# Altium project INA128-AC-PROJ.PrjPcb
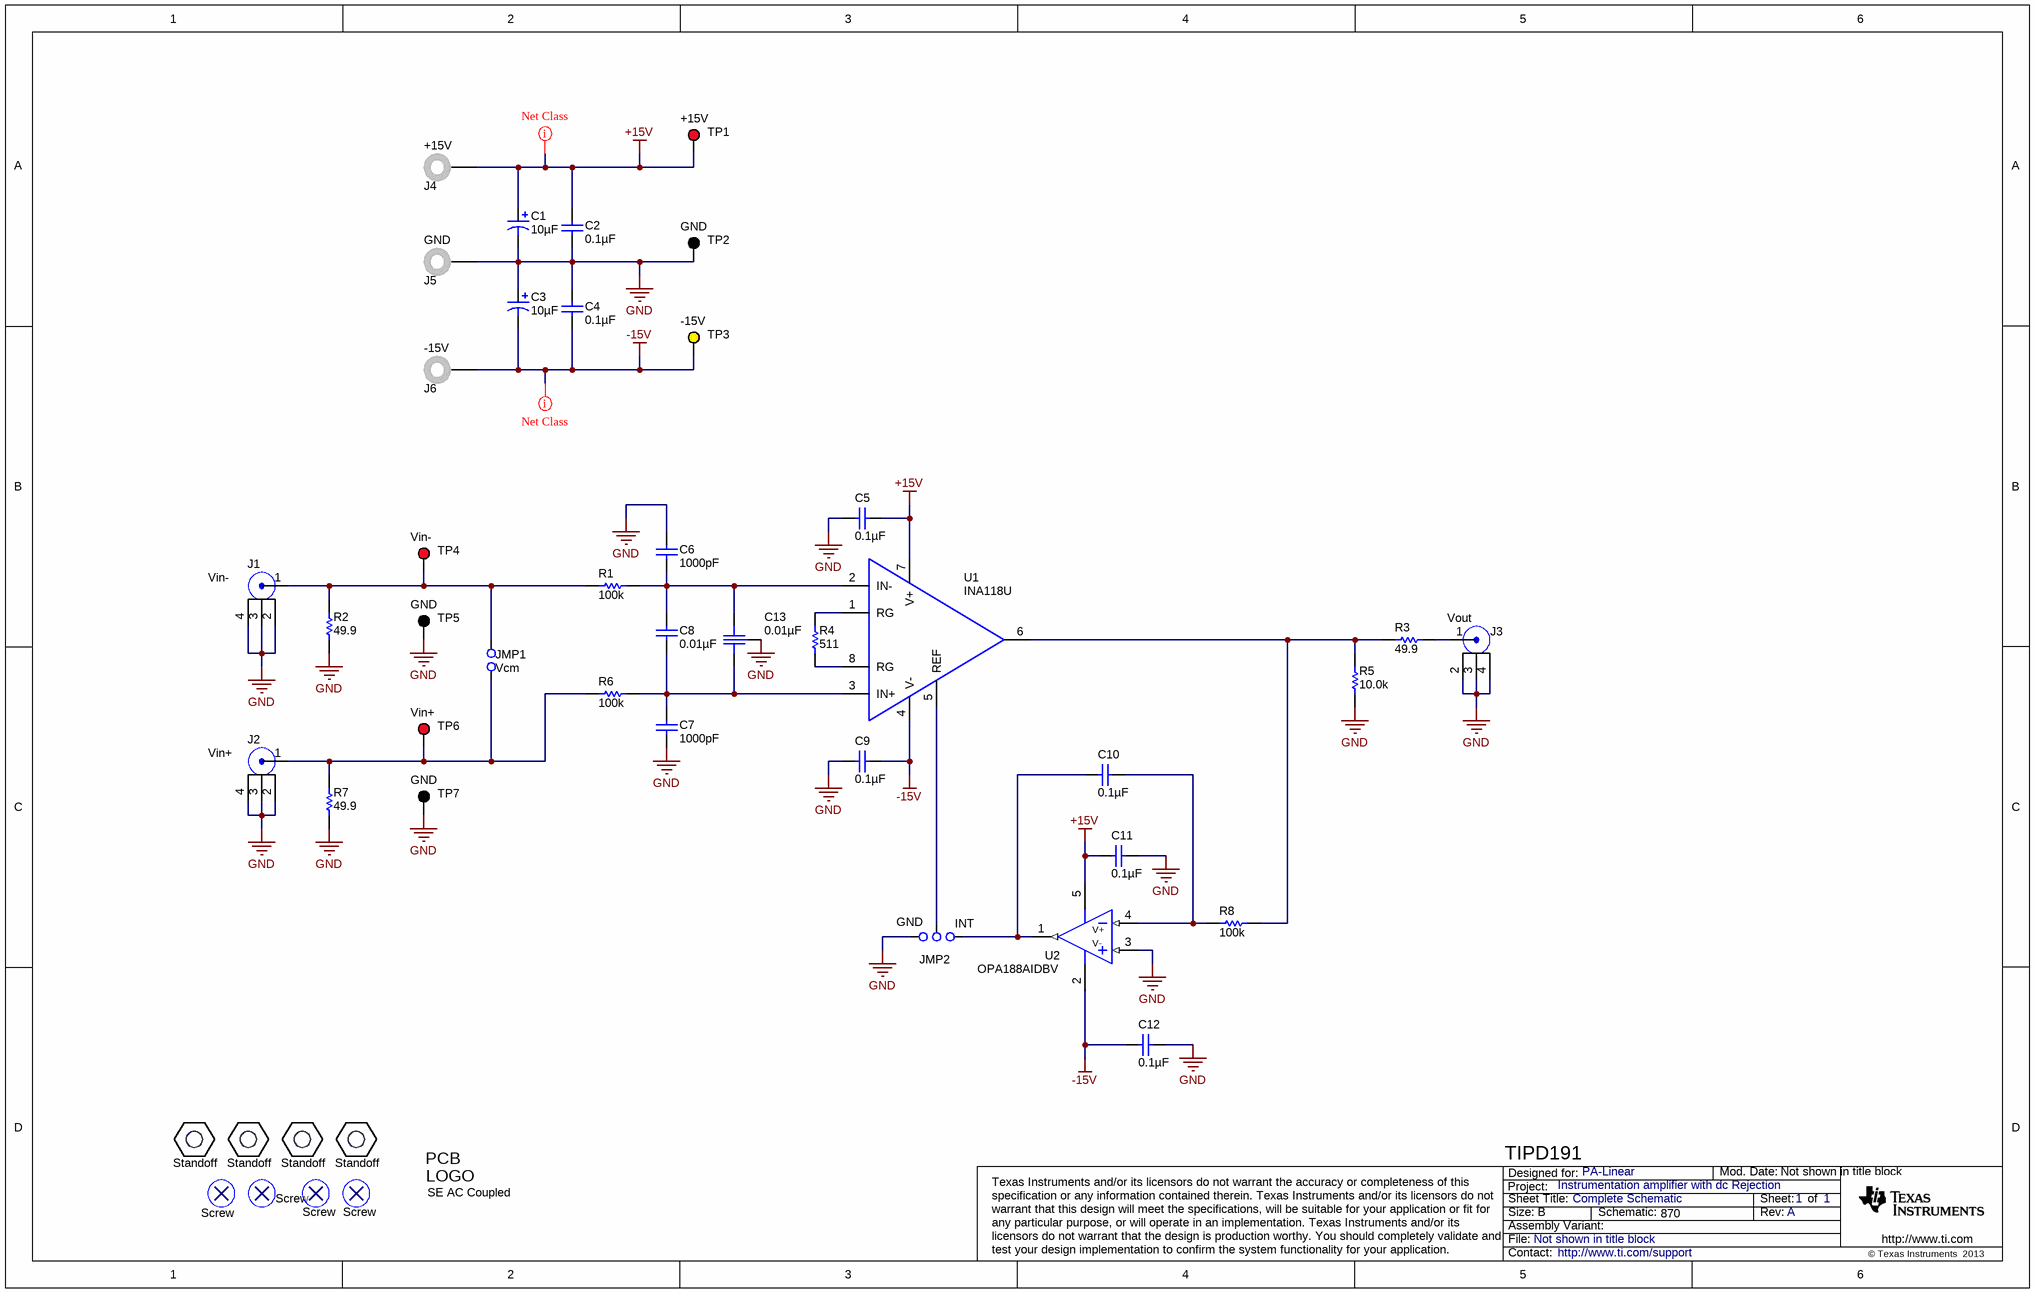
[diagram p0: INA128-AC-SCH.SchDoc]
TechSupport: http://www.ti.com/support; SCH_Rev: A; PRJ_Title: Instrumentation amplifier with dc Rejection; PRJ_Customer: PA-Linear; CopyrightYear: 2013
1 sheet, 47 parts. Net scope: global (net labels, ports and power ports of the same name join across sheets).
Board file: INA128-AC_PCB.PcbDoc

## Sheet INA128-AC-SCH.SchDoc: Complete Schematic
size B; Date: Not shown in title block; ApprovedBy: Not shown in title block; CheckedBy: Not shown in title block; Author: Not shown in title block; CompanyName: Not shown in title block; DrawnBy: Not shown in title block; Engineer: Not shown in title block; Organization: Not shown in title block; Address1: Not shown in title block; Address2: Not shown in title block; Address3: Not shown in title block; Address4: Not shown in title block; DocumentNumber: 1; Revision: Use project parameter SCH_Rev; SheetNumber: 1; SheetTotal: 1; PageSetup: Record=PageOptions|CenterHorizontal=True|CenterVertical=True|PrintScale=0.72|XCorrection=1.00|YCorrection=1.00|PrintKind=0|BorderSize=5000000|LeftOffset=0|BottomOffset=0|Orientation=2|PaperLength=1000|PaperWidth=1000|Scale=100|PaperSource=15|PrintQuality=600|MediaType=1|DitherType=10|PaperKind=Letter|PrintScaleMode=1

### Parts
C1  ValueDisplayed: 10µF  [7343-43]  (hidden comment: 293D106X9050E2TE3)
C2  ValueDisplayed: 0.1µF  [0603]  (hidden comment: 06033D104KAT2A)
C3  ValueDisplayed: 10µF  [7343-43]  (hidden comment: 293D106X9050E2TE3)
C4  ValueDisplayed: 0.1µF  [0603]  (hidden comment: 06033D104KAT2A)
C5  ValueDisplayed: 0.1µF  [0603]  (hidden comment: 06033D104KAT2A)
C6  ValueDisplayed: 1000pF  [0603]  (hidden comment: 06031C102JAT2A)
C7  ValueDisplayed: 1000pF  [0603]  (hidden comment: 06031C102JAT2A)
C8  ValueDisplayed: 0.01µF  [0603]  (hidden comment: 06031C103JAT2A)
C9  ValueDisplayed: 0.1µF  [0603]  (hidden comment: 06033D104KAT2A)
C10  ValueDisplayed: 0.1µF  [0603]  (hidden comment: 06033D104KAT2A)
C11  ValueDisplayed: 0.1µF  [0603]  (hidden comment: 06033D104KAT2A)
C12  ValueDisplayed: 0.1µF  [0603]  (hidden comment: 06033D104KAT2A)
C13  ValueDisplayed: 0.01µF  [X2Y_0603]  (hidden comment: 500X14W103MV4T)
J1  Vin-  [Right Angle BNC]
J2  Vin+  [Right Angle BNC]
J3  Vout  [Right Angle BNC]
J4  +15V  [JACK NON-INSULATED .218"]
J5  GND  [JACK NON-INSULATED .218"]
J6  -15V  [JACK NON-INSULATED .218"]
JMP1  Vcm  [Header 100mil, 1x2]
JMP2  GND  [JUMP3]
R1  ValueDisplayed: 100k  [0603]  (hidden comment: CPF0603B100KE)
R2  ValueDisplayed: 49.9  [0805]  (hidden comment: CRCW080549R9FKEA)
R3  ValueDisplayed: 49.9  [0805]  (hidden comment: CRCW080549R9FKEA)
R4  ValueDisplayed: 511  [0805]  (hidden comment: CRCW0805511RFKEA)
R5  ValueDisplayed: 10.0k  [0603]  (hidden comment: CRCW060310K0FKEA)
R6  ValueDisplayed: 100k  [0603]  (hidden comment: CPF0603B100KE)
R7  ValueDisplayed: 49.9  [0805]  (hidden comment: CRCW080549R9FKEA)
R8  ValueDisplayed: 100k  [0603]  (hidden comment: CRCW06031M00FKEA)
TIPD191  SE AC Coupled  [TI_Symbol_Overlay_Small]  (no BOM)
TP1  +15V  [Keystone5005]
TP2  GND  [Keystone5006]
TP3  -15V  [Keystone5009]
TP4  Vin-  [Keystone5005]
TP5  GND  [Keystone5006]
TP6  Vin+  [Keystone5005]
TP7  GND  [Keystone5006]
U1  INA118U  [SOIC-8 (D) low density]
U2  OPA188AIDBV  [SOT23-5 (DBV) low density]
U3  Standoff  [MHOLE1]
U4  Standoff  [MHOLE1]
U5  Standoff  [MHOLE1]
U6  Standoff  [MHOLE1]
U7  Screw  (mechanical)
U8  Screw  (mechanical)
U9  Screw  (mechanical)
U10  Screw  (mechanical)

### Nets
+15V: C1.1(+) C2.1 C5.1 C11.2 J4.1 TP1.1 U1.7(V+) U2.5(V+)
-15V: C3.2(-) C4.2 C9.1 C12.2 J6.1 TP3.1 U1.4(V-) U2.2(V-)
GND: C1.2(-) C2.2 C3.1(+) C4.1 C5.2 C6.1 C7.2 C9.2 C11.1 C12.1 C13.3 J1.2 J1.3 J1.4 J2.2 J2.3 J2.4 J3.2 J3.3 J3.4 J5.1 JMP2.1 R2.1 R5.1 R7.1 TP2.1 TP5.1 TP7.1 U2.3(IN+)
NetC6_2: C6.2 C8.1 C13.2 R1.2 U1.2(IN-)
NetC7_1: C7.1 C8.2 C13.1 R6.2 U1.3(IN+)
NetC10_1: C10.1 R8.1 U2.4(IN-)
NetC10_2: C10.2 JMP2.3 U2.1(OUT)
NetJ1_1: J1.1 JMP1.2 R1.1 R2.2 TP4.1
NetJ2_1: J2.1 JMP1.1 R6.1 R7.2 TP6.1
NetJ3_1: J3.1 R3.1
NetJMP2_2: JMP2.2 U1.5(REF)
NetR3_2: R3.2 R5.2 R8.2 U1.6(OUT)
NetR4_1: R4.1 U1.8(RG)
NetR4_2: R4.2 U1.1(RG)

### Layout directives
net class Power: +15V, -15V

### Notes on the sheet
- (near JMP2) INT
- TIPD191

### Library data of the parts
C1 C3 = 293D106X9050E2TE3: CAP, TA, 10 µF, 50 V, +/- 10%, 0.8 ohm, SMD; Manufacturer: Vishay-Sprague; Polarized: Y; CompType: Capacitor; Value: 10uF; U/M: EA; Cap_F: 0.00001; Tolerance_%: 10; Value1: 0.8 ohm; VDC_V: 50; Value2: 50V; ESR_ohm: 0.8; IRMS_A: 0.45; TaMin_C: -55; TaMax_C: 125; Cap_Case: E
C2 C4 C5 C9-C12 = 06033D104KAT2A: CAP, CERM, 0.1 µF, 25 V, +/- 10%, X5R, 0603; Manufacturer: AVX; Polarized: N; CompType: Capacitor; Value: 0.1uF; U/M: EA; Cap_F: 0.0000001; Tolerance_%: 10; ESR_ohm: 0.048; Value1: 0.048 ohm; VDC_V: 25; Value2: 25V; IRMS_A: 0.53; TaMin_C: -55; TaMax_C: 85
C6 C7 = 06031C102JAT2A: CAP, CERM, 1000 pF, 100 V, +/- 5%, X7R, 0603; Manufacturer: AVX; Polarized: N; CompType: Capacitor; Value: 1000pF; U/M: EA; Cap_F: 0.000000001; Tolerance_%: 5; ESR_ohm: 0.276; Value1: 0.276 ohm; VDC_V: 100; Value2: 100V; TaMin_C: -55; TaMax_C: 125
C8 = 06031C103JAT2A: CAP, CERM, 0.01 µF, 100 V, +/- 5%, X7R, 0603; Manufacturer: AVX; Polarized: N; CompType: Capacitor; Value: 0.01uF; U/M: EA; Cap_F: 0.00000001; Tolerance_%: 5; ESR_ohm: 0.098; Value1: 0.098 ohm; VDC_V: 100; Value2: 100V; TaMin_C: -55; TaMax_C: 125
C13 = 500X14W103MV4T: CAP, CERM, 0.01 µF, 50 V, +/- 20%, X7R, 0603; Manufacturer: Johanson Technology; SymbolCreator: a0411947; CompType: Capacitor; U/M: EA; Cap_F: 0.00000001; Value: 0.01uF; Tolerance_%: 20; Value1: Unknown; VDC_V: 50; Value2: 50V; TaMin_C: -55; TaMax_C: 125; Polarized: N; Cap_Case: 0603
J1-J3 = BNC Right Angle: Right Angle BNC Connector; Manufacturer: TE Connectivity; PartNumber: 1-1634612-0; SymbolVersion: use current date i.e. 2008-05-20; SymbolCreator: Use LDAP id; CompType: Used in some BOM reports.  Useful for finding later.; U/M: EA, IN, or GM
J4-J6 = Banana Jack, Solder: JACK NON-INSULATED .218"; Manufacturer: Keystone; PartNumber: 575-4; SymbolVersion: use current date i.e. 2008-05-20; SymbolCreator: Use LDAP id; CompType: Used in some BOM reports.  Useful for finding later.; U/M: EA, IN, or GM
JMP1 = Jumper2: Manufacturer: Used in BOM report; SymbolVersion: use current date i.e. 2008-05-20; SymbolCreator: Use a-id; CompType: Used in some BOM reports.  Useful for finding later.; U/M: EA, IN, or GM
JMP2 = JUMP3: Manufacturer: Used in BOM report; SymbolVersion: use current date i.e. 2008-05-20; SymbolCreator: Use a-id; CompType: Used in some BOM reports.  Useful for finding later.; U/M: EA, IN, or GM
R1 R6 = CPF0603B100KE: RES, 100 k, 0.1%, 0.063 W, 0603; Manufacturer: TE Connectivity; CompType: Resistor; Value: 100k; Res_ohm: 100000; Tolerance_%: 0.1; Power_W: 0.063; Value2: 0.063W; VDC_V: 50; TempCo: 25 ppm/C; EIA_Code: E192; U/M: EA
R2 R3 R7 = CRCW080549R9FKEA: RES, 49.9, 1%, 0.125 W, 0805; Manufacturer: Vishay-Dale; CompType: Resistor; Value: 49.9; Value_Code: 49R9; Tolerance_%: 1; Power_W: 0.125; Value2: 0.125W; VDC_V: 150; TempCo: 100 ppm/C; EIA_Code: E96; U/M: EA
R4 = CRCW0805511RFKEA: RES, 511, 1%, 0.125 W, 0805; Manufacturer: Vishay-Dale; CompType: Resistor; Value: 511; Value_Code: 511R; Tolerance_%: 1; Power_W: 0.125; Value2: 0.125W; VDC_V: 150; TempCo: 100 ppm/C; EIA_Code: E96; U/M: EA
R5 = CRCW060310K0FKEA: RES, 10.0 k, 1%, 0.1 W, 0603; Manufacturer: Vishay-Dale; CompType: Resistor; Value: 10.0k; Res_ohm: 10000; Value_Code: 10k0; Tolerance_%: 1; Power_W: 0.1; Value2: 0.1W; VDC_V: 75; TempCo: 100 ppm/C; EIA_Code: E96; U/M: EA
R8 = CRCW06031M00FKEA: RES, 1.00 M, 1%, 0.1 W, 0603; Manufacturer: Vishay-Dale; CompType: Resistor; Value: 1.00Meg; Res_ohm: 1000000; Value_Code: 1M00; Tolerance_%: 1; Power_W: 0.1; Value2: 0.1W; VDC_V: 75; TempCo: 100 ppm/C; EIA_Code: E96; U/M: EA
TIPD191 = TI_Logo: Texas Instrument Corporate Signature; SymbolCreator: codlsc
TP1 TP4 TP6 = 5005: Test Point, TH, Compact, Red; Manufacturer: Keystone; Alternate Manufacturer: Any; Alternate PartNumber: Equivalent; CompType: Test Point Loop; U/M: EA
TP2 TP5 TP7 = 5006: Test Point, TH, Compact, Black; Manufacturer: Keystone; Alternate Manufacturer: Any; Alternate PartNumber: Equivalent; CompType: Test Point Loop; U/M: EA
TP3 = 5009: Test Point, TH, Compact, Yellow; Manufacturer: Keystone; Alternate Manufacturer: Any; Alternate PartNumber: Equivalent; CompType: Test Point Loop; U/M: EA
U1 = INA118U: Precision, Low Power  INSTRUMENTATION AMPLIFIER, SOIC-8; Manufacturer: Texas Instruments; SymbolVersion: use current date i.e. 2008-05-20; SymbolCreator: Use a-id; CompType: Used in some BOM reports.  Useful for finding later.; U/M: EA, IN, or GM
U2 = OPA188AIDBV: Precision, Low-Noise, Rail-to-Rail Output, 36-V, Zero-Drift Operational Amplifier, SOT23-5; Manufacturer: Texas Instruments; SymbolCreator: a0411595/a0412235; CompType: OpAmp IC; U/M: EA
U3-U6 = Standoff, 1", 4-40, Alum, F-F: STANDOFF HEX 4-40THR ALUM 1"L; Manufacturer: Keystone; PartNumber: 2205; SymbolVersion: use current date i.e. 2008-05-20; SymbolCreator: Use LDAP id; CompType: Used in some BOM reports.  Useful for finding later.; U/M: EA, IN, or GM
U7-U10 = Machine Screw, 4-40, 0.25": MACHINE SCREW PAN PHILLIPS 4-40; Manufacturer: B&F Fastener Supply; PartNumber: PMSSS 440 0025 PH; SymbolVersion: use current date i.e. 2008-05-20; SymbolCreator: Use LDAP id; CompType: Mechanical; U/M: EA, IN, or GM

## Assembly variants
-100A: all parts fitted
